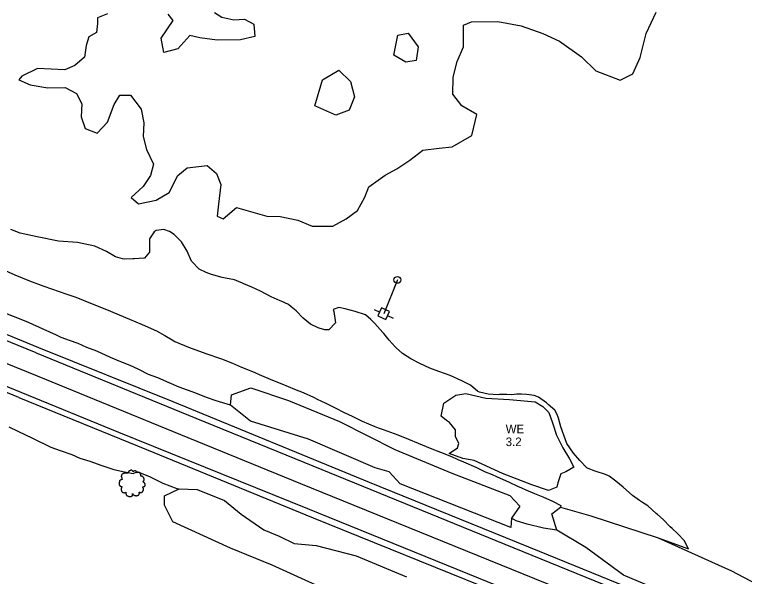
# Model space of a CAD drawing. Extents: x 2160437 to 2172832, y 205694 to 212444.
# Drawn here: x 2166012.2 to 2166437.9, y 209227.2 to 209555.1 of the extents above; entities that cross this region are included whole.
import ezdxf

# ---------------------------------------------------------------- set-up
doc = ezdxf.new("R2010")
doc.units = 0
for name, color, linetype in [('RD_EX_H2O_Pond', 7, 'Continuous'), ('RD_EX_H2O_txCode', 7, 'Continuous'), ('RD_EX_LaneStripe', 7, 'Continuous'), ('RD_EX_Road', 7, 'Continuous'), ('RD_EX_UT', 7, 'Continuous'), ('RD_EX_UT_Guy', 7, 'Continuous'), ('RD_EX_VEG', 7, 'Continuous'), ('RD_EX_VEG_ShrubLine', 7, 'Continuous'), ('RD_EX_VEG_TreeLine', 7, 'Continuous')]:
    doc.layers.add(name, color=color, linetype=linetype)

# ---------------------------------------------------------------- blocks, each defined once
blk = doc.blocks.new('T2')
at = {"layer": 'RD_EX_VEG'}
for points in [[(0.05, 7.21), (-0.25, 7.24), (-0.57, 7.14), (-0.82, 7.04), (-1.05, 6.96), (-1.27, 6.86), (-1.57, 6.69), (-1.8, 6.49), (-1.92, 6.24), (-1.97, 6.01), (-2.02, 5.74), (-2.02, 5.56), (-2.15, 5.54), (-2.3, 5.56), (-2.55, 5.64), (-2.8, 5.64), (-3.05, 5.64), (-3.4, 5.61), (-3.75, 5.61), (-4.02, 5.56), (-4.35, 5.51), (-4.72, 5.39), (-5.07, 5.26), (-5.37, 5.01), (-5.62, 4.54), (-5.75, 4.19), (-5.9, 3.94), (-5.75, 3.49), (-5.57, 3.14), (-5.55, 2.94), (-5.47, 2.52), (-5.37, 2.29), (-5.25, 2.09), (-5.32, 2.07), (-5.7, 2.02), (-6, 1.92), (-6.42, 1.69), (-6.64, 1.47), (-6.74, 1.14), (-6.77, 0.79), (-6.87, 0.59), (-6.94, 0.32), (-6.97, 0.24), (-7.02, -0.08), (-6.92, -0.53), (-6.89, -0.88), (-6.77, -1.11), (-6.62, -1.28), (-6.44, -1.53), (-6.05, -1.76), (-5.72, -1.86), (-5.52, -1.88), (-5.7, -2.38), (-5.75, -2.73), (-5.87, -3.13), (-5.87, -3.21), (-5.92, -3.68), (-5.77, -4.01), (-5.7, -4.38), (-5.52, -4.61), (-5.25, -4.91), (-4.92, -5.13), (-4.42, -5.26), (-4.02, -5.23), (-3.45, -5.06), (-3.2, -4.98), (-3.22, -5.16), (-3.2, -5.53), (-3.2, -5.96), (-3.05, -6.28), (-2.95, -6.56), (-2.8, -6.81), (-2.47, -7.03), (-2.07, -7.11), (-1.65, -7.26), (-1.2, -7.33), (-0.7, -7.36), (-0.1, -7.21), (0.18, -7.08), (0.28, -6.91), (0.48, -6.53), (0.43, -6.31), (0.45, -5.71), (0.55, -5.88), (0.73, -6.23), (1.23, -6.53), (1.63, -6.71), (2.1, -6.86), (2.4, -6.93), (2.88, -6.86), (3.25, -6.78), (3.63, -6.66), (3.93, -6.38), (4.1, -6.11), (4.15, -5.83), (4.23, -5.46), (4.28, -5.28)], [(4.28, -5.28), (4.2, -5.11), (4.15, -4.86), (4.23, -4.88), (4.4, -4.93), (4.68, -5.06), (4.9, -5.13), (5.23, -5.11), (5.5, -5.01), (5.95, -4.73), (6.22, -4.26), (6.5, -3.86), (6.57, -3.53), (6.52, -3.31), (6.5, -2.81), (6.3, -2.56), (6.25, -2.43), (6.15, -2.03), (6.22, -1.98), (6.5, -1.93), (6.87, -1.81), (7.15, -1.68), (7.37, -1.51), (7.45, -1.28), (7.42, -0.88), (7.47, -0.48), (7.4, -0.33), (7.3, -0.18), (7.22, 0.02), (7.07, 0.17), (6.97, 0.32), (6.87, 0.42), (6.75, 0.57), (6.57, 0.69), (6.42, 0.74), (6.37, 0.89), (6.52, 1.09), (6.57, 1.19), (6.6, 1.42), (6.82, 1.77), (6.87, 2.17), (6.82, 2.59), (6.77, 2.87), (6.62, 3.14), (6.42, 3.39), (6.3, 3.56), (6.12, 3.69), (5.8, 3.81), (5.55, 3.86), (5.2, 3.86), (5, 3.91), (5.03, 3.96), (5.03, 4.11), (5.03, 4.39), (4.95, 4.84), (4.8, 5.34), (4.8, 5.36), (4.7, 5.61), (4.48, 5.81), (4.3, 5.91), (4.1, 6.04), (3.85, 6.06), (3.55, 6.06), (3.28, 6.01), (3.08, 5.91), (2.9, 5.79), (2.83, 5.94), (2.73, 6.24), (2.68, 6.39), (2.53, 6.56), (2.3, 6.76), (1.85, 6.89), (1.23, 6.81), (0.93, 6.61), (0.78, 6.44), (0.73, 6.56), (0.53, 6.76), (0.43, 6.94), (0.25, 7.06), (0.1, 7.16), (0, 7.21)]]:
    blk.add_spline(points, degree=3, dxfattribs=at)
blk = doc.blocks.new('PP')
at = {"layer": 'RD_EX_UT'}
for p, q in [((2.49, 2.51), (-2.51, 2.51)), ((-2.51, 2.51), (-2.51, -2.49)), ((2.49, -2.49), (2.49, 2.51)), ((-5.94, -0.05), (-2.47, -0.05)), ((-2.51, -2.49), (2.49, -2.49)), ((2.42, -0.05), (6.06, -0.05))]:
    blk.add_line(p, q, dxfattribs=at)

msp = doc.modelspace()

# ---------------------------------------------------------------- linework, layer by layer
at = {"layer": 'RD_EX_H2O_Pond'}
msp.add_lwpolyline([(2166261.08, 209320.81), (2166262.54, 209328.32), (2166269.6, 209333.07), (2166275.42, 209333.99), (2166287.16, 209331.23), (2166300.89, 209330.39), (2166315.77, 209329.15), (2166320.37, 209326.42), (2166323.78, 209322.78), (2166325.98, 209316.86), (2166328.34, 209309.56), (2166332.06, 209302.23), (2166335.9, 209295.81), (2166338.35, 209290.99), (2166333.76, 209288.25), (2166330.84, 209286.98), (2166329.16, 209281.79), (2166328.58, 209279.29), (2166323.7, 209277.4), (2166313.96, 209280.59), (2166296.82, 209287.35), (2166280.34, 209294.89), (2166273.72, 209296.07), (2166265.79, 209298.86), (2166270.53, 209302.31), (2166271.33, 209304.77), (2166269.31, 209308.81), (2166269.3, 209312.66), (2166265.91, 209317.13), (2166264.07, 209318.26)], close=True, dxfattribs=at)
at = {"layer": 'RD_EX_LaneStripe'}
for points in [[(2165351.71, 209619.17), (2165398.66, 209599.89), (2165469.92, 209570.6), (2165540.18, 209541.69), (2165609.74, 209513.4), (2165682.5, 209484.08), (2165755.38, 209454.5), (2165825.21, 209425.99), (2165895.04, 209397.29), (2165966.21, 209368.17), (2166025.36, 209344.25)], [(2166025.36, 209344.25), (2166108.97, 209310.08), (2166179, 209281.39), (2166248.32, 209253.24), (2166322.6, 209223.02), (2166428.12, 209180.09), (2166499.44, 209151.2), (2166571.15, 209122.03), (2166642.26, 209093.12), (2166713.47, 209064.17), (2166784.54, 209035.5), (2166854.09, 209007.34), (2166996.21, 208949.61), (2167074.48, 208917.74), (2167146.55, 208888.33)]]:
    msp.add_lwpolyline(points, dxfattribs=at)
at = {"layer": 'RD_EX_Road'}
for points in [[(2165357.09, 209634.04), (2165400.48, 209616.17), (2165463.79, 209590.16), (2165519.82, 209567.3), (2165594.5, 209536.83), (2165634.04, 209521.03), (2165703.73, 209492.82), (2165783.1, 209461.45), (2165877.48, 209422.45), (2165937.8, 209397.18), (2165998.2, 209372.29), (2166026.17, 209360.72)], [(2166024.71, 209357.76), (2165943.48, 209390.77), (2165859.72, 209425.24), (2165772.07, 209461.29), (2165678.08, 209499.62), (2165598.61, 209531.58), (2165479.36, 209579.95), (2165355.66, 209630.84)], [(2165347.69, 209607.9), (2165406.01, 209584.16), (2165513.05, 209539.94), (2165598.18, 209505.37), (2165706.73, 209461.26), (2165813.54, 209417.73), (2165902.46, 209381.16), (2166015.83, 209334.81)], [(2166014.65, 209331.72), (2165949.69, 209358.32), (2165878.21, 209387.6), (2165819.58, 209411.66), (2165762.4, 209434.9), (2165704.62, 209458.26), (2165647.21, 209481.6), (2165576.85, 209510.24), (2165517.3, 209534.48), (2165418.35, 209575.15), (2165346.3, 209604.56)], [(2166026.17, 209360.72), (2166104.45, 209329.24), (2166218.97, 209282.28), (2166318.19, 209241.85), (2166429.86, 209196.42), (2166532.44, 209155.56), (2166615.15, 209121.73), (2166718.37, 209079.44), (2166758.57, 209062.93), (2166826.99, 209035.09), (2166891.12, 209009.17), (2166956.69, 208982.6), (2167013.45, 208959.75), (2167046.21, 208945.39), (2167108.06, 208919.54), (2167125.82, 208911.38), (2167128.12, 208905.84)], [(2166024.71, 209357.76), (2166117.95, 209319.57), (2166186.21, 209291.8), (2166298.24, 209246.06), (2166371.62, 209216.13), (2166463.14, 209179.26), (2166548.9, 209144.32), (2166648.16, 209104.03), (2166717.23, 209075.95), (2166755.68, 209060.57), (2166838.17, 209027.28), (2166917.84, 208994.71), (2167010.25, 208956.85), (2167067.32, 208932.42), (2167128.12, 208905.84), (2167149.74, 208896.27)], [(2166015.83, 209334.81), (2166072.81, 209311.37), (2166182.98, 209266.77), (2166282.53, 209226.31), (2166401.71, 209177.97), (2166514.59, 209132.05), (2166616.41, 209090.49), (2166709.27, 209052.8), (2166770.4, 209027.97), (2166845.06, 208997.67), (2166946.51, 208956.61), (2167027.58, 208923.96), (2167082.42, 208902.57), (2167142.85, 208879.55)], [(2166014.65, 209331.72), (2166089.07, 209301.24), (2166186.34, 209261.39), (2166293.04, 209218.16), (2166386.32, 209180.32), (2166516.17, 209127.72), (2166639.01, 209076.95), (2166708.04, 209049.04), (2166753.09, 209031.03), (2166819.33, 209004.22), (2166878.6, 208980.23), (2166936.73, 208956.62), (2166973.88, 208941.43), (2167018.87, 208923.18), (2167070.62, 208903.38), (2167105.14, 208890.26), (2167142.48, 208878.61)]]:
    msp.add_lwpolyline(points, dxfattribs=at)
at = {"layer": 'RD_EX_UT'}
msp.add_line((2166235.48, 209400.28), (2166233.7, 209395.61), dxfattribs=at)
msp.add_circle((2166235.48, 209400.28), 2, dxfattribs=at)
at = {"layer": 'RD_EX_UT_Guy'}
msp.add_lwpolyline([(2166235.48, 209400.28), (2166227.52, 209380.5)], dxfattribs=at)
at = {"layer": 'RD_EX_VEG_ShrubLine'}
for points in [[(2166066.41, 209555.55), (2166060.6, 209553.32), (2166060.53, 209549.9), (2166059.95, 209544.7), (2166055.53, 209542.13), (2166054.01, 209537.08), (2166052.94, 209530.37), (2166047.37, 209525.4), (2166041.46, 209522.94), (2166025.45, 209523.7), (2166016.39, 209519.27), (2166014.56, 209517), (2166021.24, 209514.03), (2166031.46, 209512.3), (2166041.64, 209512.5), (2166048.26, 209509.01), (2166048.26, 209509.01), (2166051.4, 209502.99), (2166050.93, 209495.38), (2166053.28, 209488.61), (2166060.35, 209485.93), (2166066.3, 209492.36), (2166070.18, 209502.72), (2166073.65, 209508.08), (2166079.75, 209508.1), (2166086.03, 209499.95), (2166087.47, 209491.95), (2166087.12, 209484.02), (2166089.1, 209476.42), (2166093.17, 209467.79), (2166091.54, 209461.25), (2166087.19, 209454.73), (2166080.12, 209448.43), (2166084.49, 209444.58), (2166094.73, 209446.75), (2166102.4, 209451.34), (2166107.49, 209461.16), (2166112.78, 209465.71), (2166124.54, 209467.02), (2166129.95, 209462.44), (2166132.48, 209455.86), (2166131.18, 209444.45), (2166130.29, 209437.4), (2166133.93, 209435.88), (2166141.71, 209442.47), (2166159.27, 209437.44), (2166167.16, 209437.37), (2166177.31, 209435.08), (2166185.73, 209431.65), (2166197.89, 209431.7), (2166205.66, 209435.89), (2166212.28, 209440.72), (2166216.57, 209448.64), (2166218.88, 209454.56), (2166218.88, 209454.56), (2166228.36, 209461.47), (2166235.17, 209465.13), (2166242.72, 209470.14), (2166250.42, 209476.04), (2166259.94, 209477.16), (2166267.46, 209477.86), (2166279, 209484.55), (2166281.79, 209496.87), (2166273.01, 209501.91), (2166267.92, 209508.77), (2166268.12, 209518.53), (2166270.44, 209527.7), (2166273.97, 209536.32), (2166274.14, 209548.98), (2166278.77, 209550.98), (2166294.06, 209551.06), (2166307.7, 209548.52), (2166320.28, 209544.18), (2166330.12, 209539.62), (2166342.8, 209530.43), (2166351.31, 209522.39), (2166365.37, 209516.78), (2166372.86, 209520.61), (2166377.09, 209530), (2166380.69, 209544.12), (2166386.41, 209556.56)], [(2166128.85, 209556.42), (2166133.14, 209553.6), (2166140.16, 209552.03), (2166146.23, 209552.41), (2166151.76, 209549.5), (2166152.41, 209542.4), (2166143.96, 209540.34), (2166130.25, 209540.17), (2166120.15, 209541.57), (2166114.48, 209542.91), (2166107.43, 209535.23), (2166099.14, 209532.92), (2166097.64, 209541.4), (2166104.72, 209551.61), (2166101.73, 209555.3)], [(2166387.68, 209249.66), (2166387.68, 209249.66), (2166405.41, 209243.25), (2166402.79, 209248.22), (2166399.05, 209252.06), (2166395.71, 209255.19), (2166394.62, 209256.22), (2166390.45, 209260.44), (2166387.17, 209263.42), (2166386.53, 209264.01), (2166381.52, 209268.37), (2166378.5, 209270.33), (2166376.79, 209271.46), (2166372.67, 209274.46), (2166367.28, 209279.29), (2166367.28, 209279.29), (2166362.99, 209282.84), (2166359.13, 209285.73), (2166356.81, 209286.59), (2166356.81, 209286.59), (2166350.85, 209288.55), (2166346.69, 209290.25), (2166346.09, 209290.52), (2166341.87, 209294.76), (2166341.87, 209294.76), (2166338.24, 209299.1), (2166334.26, 209304.8), (2166334.26, 209304.8), (2166332.52, 209309.6), (2166330.87, 209314.49), (2166330.87, 209314.49), (2166329.51, 209319.61), (2166328.74, 209321.76), (2166327.25, 209324.17), (2166323.5, 209327.6), (2166322.51, 209328.47), (2166317.72, 209331.83), (2166315.27, 209332.81), (2166311.06, 209333.45), (2166307.84, 209333.51), (2166305.25, 209333.48), (2166302.07, 209333.11), (2166299.29, 209333.34), (2166295.15, 209333.34), (2166294.22, 209333.28), (2166288.47, 209333.59), (2166283.47, 209334.76), (2166282.38, 209335.13), (2166278.21, 209338.81), (2166273.13, 209341.4), (2166273.13, 209341.4), (2166266.34, 209344.46), (2166259.6, 209346.71), (2166254.35, 209348.66), (2166248.52, 209351.46), (2166243.31, 209354.29), (2166243.31, 209354.29), (2166238.51, 209357.24), (2166234.79, 209360.59), (2166234.21, 209361.16), (2166230.74, 209365.06), (2166227.54, 209368.9), (2166226.95, 209369.59), (2166222.31, 209374.75), (2166220.08, 209377.13), (2166216.81, 209379.87), (2166210.87, 209381.88), (2166210.87, 209381.88), (2166205.07, 209383.41), (2166201.29, 209384.09), (2166198.07, 209383.08), (2166198.44, 209381.89), (2166199.41, 209375.27), (2166199.41, 209375.27), (2166195.58, 209371.16), (2166193.19, 209371.04), (2166189.91, 209372.04), (2166189.24, 209372.28), (2166184.72, 209374.38), (2166180.57, 209377.99), (2166180.57, 209377.99), (2166176.53, 209382.21), (2166173.52, 209384.59), (2166171.92, 209385.85), (2166167.63, 209387.78), (2166167.03, 209388.05), (2166161.86, 209390.44), (2166155.67, 209393.77), (2166150.53, 209395.97), (2166145.91, 209397.98), (2166145.21, 209398.3), (2166140.45, 209400.26), (2166135.14, 209401.27), (2166133.21, 209401.66), (2166127.03, 209403.42), (2166123.95, 209404.57), (2166119.9, 209406.52), (2166115.44, 209411.17), (2166115.44, 209411.17), (2166112.83, 209417.09), (2166109.57, 209422.4), (2166109.57, 209422.4), (2166105.23, 209426.76), (2166102.63, 209428.47), (2166099.17, 209429.73), (2166094.74, 209429.08), (2166093.62, 209428.33), (2166090.96, 209424.18), (2166090.91, 209423.78), (2166090.85, 209416.72), (2166090.89, 209416.4), (2166087.87, 209412.9), (2166087.57, 209412.91), (2166082.1, 209412.49), (2166081.06, 209412.59), (2166076.48, 209412.43), (2166075.03, 209412.55), (2166071.06, 209413.74), (2166065.72, 209416.8), (2166058.97, 209419.96), (2166048.91, 209422.07), (2166037.74, 209422.9), (2166025.25, 209425.46), (2166015.36, 209427.53), (2166010.06, 209429.71)], [(2165999.45, 209408.8), (2166012.38, 209403.15), (2166020.79, 209399.68), (2166029.16, 209396.64), (2166042.57, 209391.86), (2166047.86, 209390.14), (2166057.38, 209386.33), (2166065.81, 209382.9), (2166079.17, 209377.36), (2166086.63, 209374.3), (2166094.87, 209370.59), (2166099.73, 209367.8), (2166104.1, 209365.23), (2166105.71, 209364.38), (2166113.59, 209361.07), (2166123.81, 209357.37), (2166132.79, 209354.23), (2166139.34, 209351.7), (2166144.63, 209349.31), (2166149.9, 209347.12), (2166152.24, 209346.19), (2166154.88, 209345.12), (2166162.67, 209341.73), (2166168.07, 209339.6), (2166175.48, 209336.56), (2166180.54, 209334.46), (2166186.45, 209331.86), (2166188.71, 209330.6), (2166193.75, 209328.33), (2166199.53, 209325.43), (2166204.14, 209322.99), (2166209.41, 209320.55), (2166210.99, 209319.78), (2166214.94, 209317.89), (2166222.25, 209314.65), (2166224.22, 209313.95), (2166227.17, 209313.04), (2166235.66, 209309.87), (2166242.04, 209307.24), (2166247.67, 209305.06), (2166252.26, 209303.12), (2166254.63, 209302.11), (2166260.68, 209299.81), (2166267.06, 209297.17), (2166270.74, 209295.46), (2166274.1, 209294), (2166281.17, 209290.88), (2166286.74, 209288.19), (2166290.73, 209286.63), (2166293.4, 209285.49), (2166300.62, 209282.18), (2166305.49, 209279.92), (2166307.93, 209278.94), (2166310.48, 209277.8), (2166315.52, 209275.52), (2166319.29, 209274.01), (2166320.41, 209273.56), (2166325.93, 209271.02), (2166330.85, 209268.62), (2166330.57, 209267.7)], [(2166138.04, 209327.12), (2166129.71, 209329.67), (2166124.18, 209331.68), (2166117.93, 209334.2), (2166108.1, 209337.72), (2166102.27, 209340.11), (2166095.65, 209343.03), (2166090.22, 209345.11), (2166084.72, 209347.96), (2166081.7, 209349.25), (2166079.55, 209350.22), (2166074.14, 209352.48), (2166068.2, 209355.03), (2166060.14, 209358.61), (2166054.38, 209360.9), (2166049.31, 209363.24), (2166044.15, 209364.85), (2166039.39, 209366.57), (2166036.57, 209367.95), (2166018.87, 209376.05), (2165997.62, 209384.45)], [(2166008.81, 209314.48), (2166014.14, 209312.02), (2166022.69, 209307.93), (2166033.32, 209302.72), (2166038.82, 209300.66), (2166045.46, 209298.33), (2166050.13, 209296.29), (2166056.06, 209294.4), (2166056.06, 209294.4), (2166063.1, 209292.01), (2166070.03, 209289.67), (2166076.32, 209288.16), (2166081.43, 209287.36), (2166083.55, 209288.2), (2166084.04, 209288.22)], [(2166084.04, 209288.22), (2166091.29, 209285.26), (2166098.72, 209281.61), (2166106.84, 209278.43), (2166108.19, 209278.41)], [(2166328.42, 209254.25), (2166320.8, 209255.34), (2166311.29, 209257.7), (2166304.69, 209259.72), (2166302.06, 209261.29)]]:
    msp.add_lwpolyline(points, dxfattribs=at)
for points in [[(2166233.49, 209531.48), (2166235.74, 209543.19), (2166241.87, 209544.28), (2166247.64, 209536.27), (2166246.44, 209528.28), (2166240.4, 209527.4)], [(2166187.34, 209501.92), (2166191.78, 209517.1), (2166201.37, 209522.63), (2166208.11, 209515.99), (2166210.52, 209507.22), (2166207.41, 209499.25), (2166199.63, 209496.38)]]:
    msp.add_lwpolyline(points, close=True, dxfattribs=at)
at = {"layer": 'RD_EX_VEG_TreeLine'}
for points in [[(2166149.7, 209317.78), (2166138.04, 209327.12), (2166138.78, 209333.15), (2166149.96, 209337.31), (2166171.96, 209329.86), (2166201.67, 209317.68), (2166234.03, 209301.36), (2166267.33, 209287.39), (2166301.09, 209274.34), (2166306.93, 209268.23), (2166302.06, 209261.29), (2166301.73, 209255.67), (2166237.09, 209281.27), (2166230.7, 209288.18), (2166222.56, 209290.64), (2166183.6, 209307.35)], [(2166328.42, 209254.25), (2166325.68, 209263.78), (2166330.57, 209267.7), (2166348.33, 209262.46), (2166387.68, 209249.66), (2166430.38, 209230.55), (2166455.81, 209217), (2166466.1, 209204.91), (2166465.06, 209199.13), (2166461.18, 209196.38), (2166444.01, 209195.55), (2166367.34, 209227.89), (2166345.43, 209244.07)]]:
    msp.add_lwpolyline(points, close=True, dxfattribs=at)
msp.add_lwpolyline([(2166207.26, 209213.37), (2166162.5, 209233.77), (2166138.05, 209243.64), (2166104.4, 209259.1), (2166099.6, 209268.71), (2166099.54, 209274.32), (2166108.19, 209278.41), (2166118.76, 209277.85), (2166134.63, 209271.48), (2166144.39, 209263.61), (2166157.65, 209254.39), (2166166.46, 209250.6), (2166175.36, 209246.47), (2166188.14, 209245.25), (2166211.46, 209239.13), (2166240.78, 209226.88)], dxfattribs=at)

# ---------------------------------------------------------------- block references
at = {"layer": 'RD_EX_UT', "xscale": 1.0199999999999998, "yscale": 1.0200000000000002, "rotation": -24.757605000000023}
msp.add_blockref('PP', (2166227.52, 209380.5), dxfattribs=at)
at = {"layer": 'RD_EX_VEG', "xscale": 1.0499999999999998, "yscale": 1.0499999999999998}
msp.add_blockref('T2', (2166080.5, 209281.56), dxfattribs=at)

# ---------------------------------------------------------------- texts
at = {"layer": 'RD_EX_H2O_txCode'}
for s, p in [('WE', (2166298.68, 209310.76)), ('3.2', (2166298.68, 209303.26))]:
    msp.add_text(s, height=5, dxfattribs=at).set_placement(p)

doc.saveas('drawing.dxf')
